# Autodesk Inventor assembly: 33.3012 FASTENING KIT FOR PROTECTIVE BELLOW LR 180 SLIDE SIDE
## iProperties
Created: 2007-06
Part Number: 33.3012 FASTENING KIT FOR PROTECTIVE BELLOW LR 180 SLIDE SIDE
Document SubType Name: Assembly
Designer: Andy Moles
Author: Andy Moles
